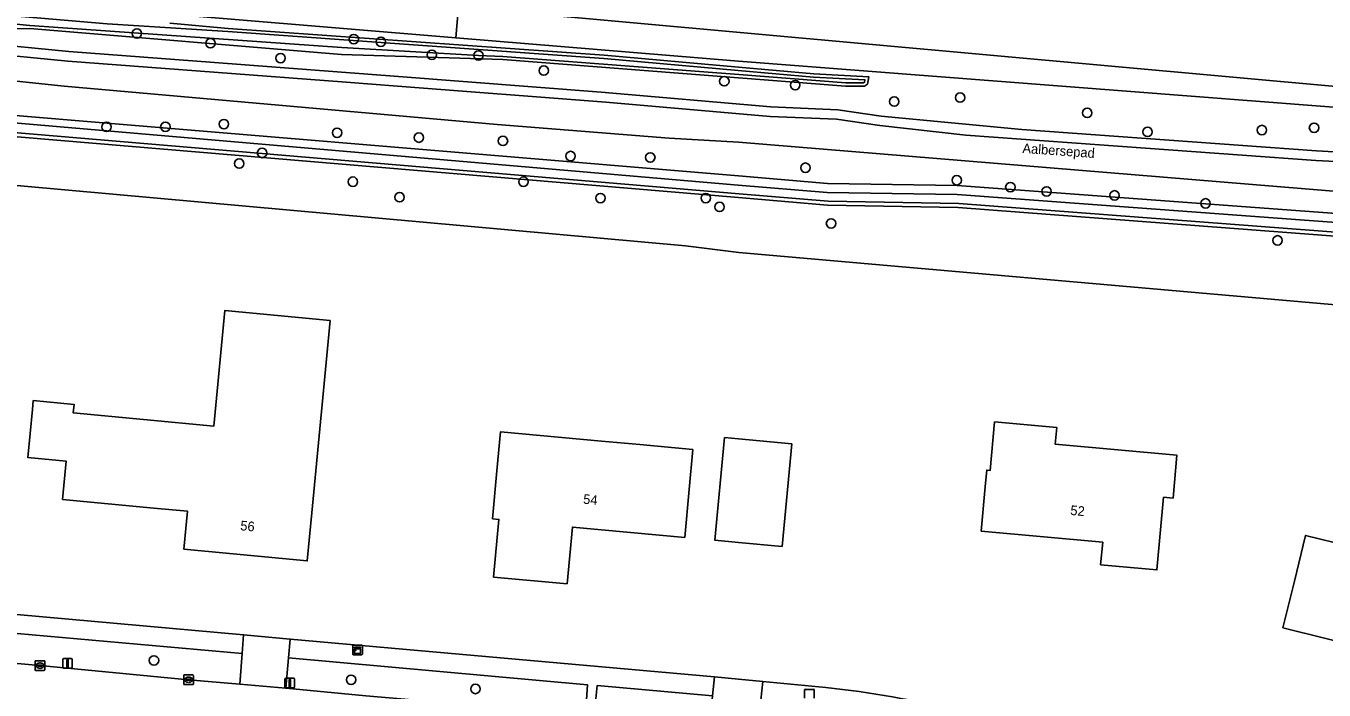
# Model space of a CAD drawing. Extents: x 162722 to 165104, y 384719 to 386284.
# Drawn here: x 163926.1 to 164060.8, y 385187.3 to 385256.2 of the extents above; entities that cross this region are included whole.
import ezdxf

# ---------------------------------------------------------------- set-up
doc = ezdxf.new("R2010")
doc.units = 0
for name, color, linetype in [('IMGEO_Boom', 7, 'Continuous'), ('IMGEO_Brandkraan', 7, 'Continuous'), ('IMGEO_Erf', 7, 'Continuous'), ('IMGEO_Gemengd_bos', 7, 'Continuous'), ('IMGEO_Grasland_agrarisch', 7, 'Continuous'), ('IMGEO_Groenvoorziening', 7, 'Continuous'), ('IMGEO_Kast', 7, 'Continuous'), ('IMGEO_Kolk', 7, 'Continuous'), ('IMGEO_Lichtmast', 7, 'Continuous'), ('IMGEO_Loofbos', 7, 'Continuous'), ('IMGEO_Oever', 7, 'Continuous'), ('IMGEO_Openbare_ruimte_label', 7, 'Continuous'), ('IMGEO_Pand', 7, 'Continuous'), ('IMGEO_Pand_nummerreeks', 7, 'Continuous'), ('IMGEO_Rijbaan_lokaal_gesloten', 7, 'Continuous'), ('IMGEO_Rijbaan_lokaal_halfverhard', 7, 'Continuous'), ('IMGEO_Voetpad_open', 7, 'Continuous'), ('IMGEO_Waterloop', 7, 'Continuous')]:
    doc.layers.add(name, color=color, linetype=linetype)

msp = doc.modelspace()

# ---------------------------------------------------------------- linework, layer by layer
at = {"layer": 'IMGEO_Boom'}
for centre in [(163937.58, 385255.46), (163945.21, 385254.45), (163960.08, 385254.88), (163962.89, 385254.6), (163952.48, 385252.91), (163968.18, 385253.25), (163973.01, 385253.18), (163979.79, 385251.61), (163998.53, 385250.51), (164005.89, 385250.1), (164023, 385248.81), (164016.16, 385248.4), (163946.6, 385246.05), (164036.19, 385247.22), (163934.43, 385245.77), (163940.53, 385245.78), (163958.35, 385245.15), (163966.84, 385244.65), (164042.45, 385245.24), (164054.31, 385245.44), (164059.72, 385245.68), (163975.56, 385244.31), (163948.19, 385241.96), (163950.56, 385243.06), (163982.58, 385242.74), (163990.85, 385242.59), (164006.94, 385241.53), (163959.99, 385240.08), (163977.68, 385240.08), (164022.65, 385240.22), (164028.21, 385239.52), (163964.83, 385238.47), (163985.68, 385238.38), (163996.61, 385238.38), (164031.97, 385239.07), (164039.02, 385238.66), (163998.04, 385237.46), (164048.47, 385237.83), (164009.6, 385235.75), (164055.94, 385233.99), (163939.35, 385190.39), (163959.8, 385188.38), (163972.7, 385187.43)]:
    msp.add_circle(centre, 0.489, dxfattribs=at)
at = {"layer": 'IMGEO_Brandkraan'}
for p, q in [((164006.86, 385186.47), (164006.86, 385187.32)), ((164006.94, 385187.39), (164007.79, 385187.39)), ((164007.86, 385187.32), (164007.86, 385186.47))]:
    msp.add_line(p, q, dxfattribs=at)
for points in [[(164006.86, 385186.47), (164006.86, 385187.32)], [(164006.94, 385187.39), (164007.79, 385187.39)], [(164007.86, 385187.32), (164007.86, 385186.47)]]:
    msp.add_lwpolyline(points, dxfattribs=at)
for centre, start, end in [((164006.94, 385187.32), 91.552, 178.448), ((164006.94, 385187.32), 91.552, 178.448), ((164007.79, 385187.32), 1.552, 88.448), ((164007.79, 385187.32), 1.552, 88.448)]:
    msp.add_arc(centre, 0.0765, start, end, dxfattribs=at)
at = {"layer": 'IMGEO_Erf'}
msp.add_lwpolyline([(164131.6, 385206.91), (164130.71, 385209.11), (164120.89, 385213.87), (164102.71, 385215.68), (164099.68, 385223.88), (164071.61, 385226.26), (164069.06, 385226.66), (164000.03, 385232.74), (163994.49, 385233.42), (163921.24, 385240.04), (163917.36, 385195.85), (163948.65, 385193.05), (163953.49, 385192.61), (163997.5, 385188.68), (164000, 385188.45), (164002.51, 385188.22), (164009.05, 385187.59)], dxfattribs=at)
for points in [[(163955.73, 385205.7), (163955.26, 385200.72), (163942.46, 385201.93), (163942.83, 385205.88), (163939.34, 385206.21), (163929.86, 385207.11), (163930.24, 385211.07), (163926.26, 385211.45), (163926.73, 385216.42), (163926.82, 385217.36), (163931.05, 385216.96), (163930.96, 385216.09), (163945.56, 385214.71), (163946.7, 385226.7), (163957.62, 385225.67)], [(164025.18, 385203.81), (164025.64, 385208.79), (164025.76, 385210.15), (164026.12, 385210.11), (164026.58, 385215.14), (164033.02, 385214.55), (164032.86, 385212.83), (164045.49, 385211.68), (164045.09, 385207.24), (164044.11, 385207.33), (164043.42, 385199.78), (164037.57, 385200.32), (164037.79, 385202.66)], [(163994.88, 385208.13), (163994.42, 385203.15), (163982.76, 385204.23), (163982.21, 385198.35), (163974.59, 385199.05), (163975.14, 385205.02), (163974.48, 385205.09), (163974.94, 385210.06), (163975.32, 385214.13), (163985.78, 385213.16), (163989.76, 385212.79), (163995.26, 385212.28)], [(164004.53, 385202.21), (164000, 385202.64), (163997.56, 385202.86), (163998.55, 385213.52), (164000, 385213.38), (164005.52, 385212.87)], [(164056.48, 385193.77), (164057.68, 385198.62), (164058.84, 385203.37), (164072.42, 385200.03), (164077.49, 385202.76), (164086.52, 385200.54), (164086.3, 385199.67), (164085.11, 385194.81), (164078.55, 385196.42), (164075.39, 385194.51), (164073.01, 385184.84), (164064.14, 385187.01), (164065.27, 385191.61)]]:
    msp.add_lwpolyline(points, close=True, dxfattribs=at)
msp.add_arc((163996.85, 385075.9), 112.35, 69.4969, 83.767, dxfattribs=at)
at = {"layer": 'IMGEO_Gemengd_bos'}
msp.add_lwpolyline([(164100.55, 385231.49), (164022.81, 385237.41), (164009.25, 385237.64), (164000, 385238.42), (163921.82, 385245), (163921.24, 385240.04), (163994.49, 385233.42), (164000.03, 385232.74), (164069.06, 385226.66)], dxfattribs=at)
at = {"layer": 'IMGEO_Grasland_agrarisch'}
for points in [[(164074.75, 385390.56), (164014.8, 385394.87), (164000, 385395.93), (163986.38, 385396.95), (163984.62, 385362.03), (163943.73, 385354), (163942.75, 385342.54), (163942.72, 385342.22), (163934.45, 385258.02), (163970.67, 385255.02), (163970.96, 385258.24), (163974.78, 385302.89), (164000, 385323.52), (164026.82, 385345.17), (164070.61, 385341.89), (164074.39, 385386.44)], [(164066.33, 385295.02), (164004.39, 385300.42), (164000, 385300.8), (163979.59, 385302.53), (163976.14, 385257.74), (164063.13, 385249.85), (164063.14, 385250)]]:
    msp.add_lwpolyline(points, close=True, dxfattribs=at)
at = {"layer": 'IMGEO_Groenvoorziening'}
for points in [[(164073.51, 385238.14), (164000, 385244.17), (163992.8, 385244.6), (163974.96, 385246.02), (163930.03, 385250), (163915.82, 385251.48), (163915.72, 385250.35), (163915.69, 385250.09), (163910.82, 385250.52), (163910.84, 385250.78), (163910.93, 385251.8), (163905.68, 385252.15), (163892.24, 385253.74), (163848.3, 385257.56)], [(163884.6, 385257.26), (163895.05, 385256.23), (163909.94, 385254.43), (163911.16, 385254.33), (163911.2, 385254.75), (163916.07, 385254.41), (163916.03, 385253.92), (163921.2, 385253.48), (163930.41, 385252.6), (163945.57, 385251.44), (163959.29, 385250.4), (163964.63, 385249.99), (163986.23, 385248.34), (164003.27, 385246.86), (164010.18, 385246.55), (164014.67, 385245.9), (164023.58, 385244.91), (164029.32, 385244.49), (164059.9, 385242.29), (164066, 385241.95)], [(164133.98, 385237.82), (164110.27, 385239.27), (164101.43, 385239.79), (164090.14, 385240.67), (164066.08, 385242.94), (164059.97, 385243.29), (164029.39, 385245.49), (164014.82, 385246.89), (164010.32, 385247.54), (164003.34, 385247.86), (163985.76, 385249.38), (163964.71, 385250.98), (163945.64, 385252.44), (163930.5, 385253.6), (163921.3, 385254.48), (163910.06, 385255.42), (163896, 385257.12)], [(163834.56, 385255.03), (163855.76, 385254), (163892.66, 385250), (163911.85, 385247.92), (163911.69, 385246.81), (163911.59, 385246.09), (163912.34, 385245.98), (163914.64, 385245.63), (163915.09, 385245.57), (163915.21, 385246.44), (163915.39, 385247.75), (164000, 385240.67), (164009.22, 385239.9), (164022.69, 385239.69), (164100.92, 385233.9)]]:
    msp.add_lwpolyline(points, dxfattribs=at)
for points in [[(163948.49, 385191.1), (163914.22, 385194.16), (163914.18, 385191.04), (163916.96, 385190.8), (163927.52, 385189.85), (163942.93, 385188.39), (163948.26, 385187.94)], [(163984.32, 385187.87), (163953.32, 385190.65), (163953.03, 385187.5), (163961.33, 385186.71), (163982.73, 385184.89), (163984.11, 385184.77)], [(163997.31, 385186.71), (163985.32, 385187.78), (163985.03, 385184.69), (163997.04, 385183.65)]]:
    msp.add_lwpolyline(points, close=True, dxfattribs=at)
at = {"layer": 'IMGEO_Kast'}
for p, q in [((163959.98, 385191.06), (163959.98, 385191.9)), ((163959.98, 385191.9), (163959.98, 385191.06)), ((163960.05, 385191.98), (163960.89, 385191.98)), ((163960.89, 385191.98), (163960.05, 385191.98)), ((163960.97, 385191.91), (163960.97, 385191.07)), ((163960.97, 385191.07), (163960.97, 385191.91)), ((163960.9, 385190.98), (163960.06, 385190.98)), ((163960.06, 385190.98), (163960.9, 385190.98))]:
    msp.add_line(p, q, dxfattribs=at)
for points in [[(163960.17, 385191.77), (163960.77, 385191.77), (163960.77, 385191.69), (163960.17, 385191.69), (163960.17, 385191.77)], [(163960.17, 385191.6), (163960.77, 385191.6), (163960.77, 385191.11), (163960.17, 385191.11), (163960.17, 385191.6)]]:
    msp.add_lwpolyline(points, dxfattribs=at)
msp.add_circle((163960.25, 385191.44), 0.0377, dxfattribs=at)
for centre, start, end in [((163960.05, 385191.9), 92.4484, 184.2845), ((163960.05, 385191.9), 92.4484, 184.2845), ((163960.9, 385191.9), 2.4484, 94.2845), ((163960.9, 385191.9), 2.4484, 94.2845), ((163960.05, 385191.06), 182.4484, 274.2845), ((163960.05, 385191.06), 182.4484, 274.2845), ((163960.9, 385191.06), 272.4484, 4.2845), ((163960.9, 385191.06), 272.4484, 4.2845)]:
    msp.add_arc(centre, 0.0779, start, end, dxfattribs=at)
at = {"layer": 'IMGEO_Kolk'}
for p, q in [((163927.02, 385189.43), (163927.02, 385190.28)), ((163927.09, 385190.36), (163927.94, 385190.36)), ((163927.51, 385190.13), (163927.53, 385190.13)), ((163928.02, 385190.28), (163928.02, 385189.43)), ((163927.94, 385189.35), (163927.09, 385189.35)), ((163927.28, 385189.85), (163927.28, 385189.86)), ((163927.32, 385189.9), (163927.72, 385189.9)), ((163927.71, 385189.81), (163927.32, 385189.81)), ((163927.53, 385189.58), (163927.5, 385189.58)), ((163927.76, 385189.86), (163927.76, 385189.85)), ((163942.43, 385187.96), (163942.43, 385188.81)), ((163942.51, 385188.89), (163943.36, 385188.89)), ((163942.92, 385188.67), (163942.95, 385188.67)), ((163943.44, 385188.81), (163943.44, 385187.96)), ((163943.36, 385187.89), (163942.51, 385187.89)), ((163942.69, 385188.38), (163942.69, 385188.39)), ((163943.13, 385188.34), (163942.73, 385188.34)), ((163942.74, 385188.43), (163943.13, 385188.43)), ((163942.94, 385188.11), (163942.92, 385188.11)), ((163943.18, 385188.39), (163943.18, 385188.38))]:
    msp.add_line(p, q, dxfattribs=at)
for points in [[(163927.02, 385189.43), (163927.02, 385190.28)], [(163927.09, 385190.36), (163927.94, 385190.36)], [(163928.02, 385190.28), (163928.02, 385189.43)], [(163927.94, 385189.35), (163927.09, 385189.35)], [(163942.43, 385187.96), (163942.43, 385188.81)], [(163942.51, 385188.89), (163943.36, 385188.89)], [(163943.44, 385188.81), (163943.44, 385187.96)], [(163943.36, 385187.89), (163942.51, 385187.89)]]:
    msp.add_lwpolyline(points, dxfattribs=at)
for centre, radius, start, end in [((163927.09, 385190.28), 0.0765, 91.552, 178.448), ((163927.09, 385190.28), 0.0765, 91.552, 178.448), ((163927.94, 385190.28), 0.0765, 1.552, 88.448), ((163927.94, 385190.28), 0.0765, 1.552, 88.448), ((163927.09, 385189.43), 0.0765, 181.552, 268.448), ((163927.09, 385189.43), 0.0765, 181.552, 268.448), ((163927.32, 385189.86), 0.0403, 85.8775, 175.7526), ((163927.31, 385189.85), 0.0366, 178.938, 274.7102), ((163927.72, 385189.85), 0.043, 264.8664, 352.4533), ((163927.72, 385189.86), 0.0386, 1.7309, 96.639), ((163927.94, 385189.43), 0.0765, 271.552, 358.448), ((163927.94, 385189.43), 0.0765, 271.552, 358.448), ((163942.51, 385188.81), 0.0765, 91.552, 178.448), ((163942.51, 385188.81), 0.0765, 91.552, 178.448), ((163943.36, 385188.81), 0.0765, 1.552, 88.448), ((163943.36, 385188.81), 0.0765, 1.552, 88.448), ((163942.51, 385187.96), 0.0765, 181.552, 268.448), ((163942.51, 385187.96), 0.0765, 181.552, 268.448), ((163942.73, 385188.39), 0.0403, 85.8775, 175.7526), ((163942.73, 385188.38), 0.0366, 178.938, 274.7102), ((163943.14, 385188.39), 0.0386, 1.7309, 96.639), ((163943.13, 385188.39), 0.043, 264.8664, 352.4533), ((163943.36, 385187.96), 0.0765, 271.552, 358.448), ((163943.36, 385187.96), 0.0765, 271.552, 358.448)]:
    msp.add_arc(centre, radius, start, end, dxfattribs=at)
for centre, major_axis, ratio, start_param, end_param in [((163927.5, 385189.85), (-0.387, 0.002), 0.722429, 4.712389, 7.853982), ((163927.53, 385189.85), (-0.39, 0.002), 0.717154, 1.570796, 4.712389), ((163942.92, 385188.39), (-0.387, 0.002), 0.722429, 4.712389, 7.853982), ((163942.95, 385188.39), (-0.39, 0.002), 0.717154, 1.570796, 4.712389)]:
    msp.add_ellipse(centre, major_axis=major_axis, ratio=ratio, start_param=start_param, end_param=end_param, dxfattribs=at)
at = {"layer": 'IMGEO_Lichtmast'}
for p, q in [((163929.88, 385189.69), (163929.88, 385190.49)), ((163929.88, 385190.49), (163929.88, 385189.69)), ((163929.98, 385190.59), (163930.77, 385190.59)), ((163930.77, 385190.59), (163929.98, 385190.59)), ((163930.87, 385190.49), (163930.87, 385189.69)), ((163930.87, 385189.69), (163930.87, 385190.49)), ((163930.77, 385189.59), (163929.98, 385189.59)), ((163929.98, 385189.59), (163930.77, 385189.59)), ((163952.94, 385187.64), (163952.94, 385188.44)), ((163952.94, 385188.44), (163952.94, 385187.64)), ((163953.04, 385188.54), (163953.83, 385188.54)), ((163953.83, 385188.54), (163953.04, 385188.54)), ((163953.83, 385187.54), (163953.04, 385187.54)), ((163953.04, 385187.54), (163953.83, 385187.54)), ((163953.93, 385188.44), (163953.93, 385187.64)), ((163953.93, 385187.64), (163953.93, 385188.44))]:
    msp.add_line(p, q, dxfattribs=at)
for points in [[(163930.3, 385190.47), (163930.45, 385190.47), (163930.45, 385189.72), (163930.3, 385189.72), (163930.3, 385190.47)], [(163953.36, 385188.42), (163953.51, 385188.42), (163953.51, 385187.67), (163953.36, 385187.67), (163953.36, 385188.42)]]:
    msp.add_lwpolyline(points, dxfattribs=at)
for centre, start, end in [((163929.98, 385190.49), 90, 180), ((163929.98, 385190.49), 90, 180), ((163930.77, 385190.49), 0, 90), ((163930.77, 385190.49), 360, 90), ((163929.98, 385189.69), 180, 270), ((163929.98, 385189.69), 180, 270), ((163930.77, 385189.69), 270, 0), ((163930.77, 385189.69), 270, 0), ((163953.04, 385188.44), 90, 180), ((163953.04, 385188.44), 90, 180), ((163953.04, 385187.64), 180, 270), ((163953.04, 385187.64), 180, 270), ((163953.83, 385188.44), 0, 90), ((163953.83, 385188.44), 360, 90), ((163953.83, 385187.64), 270, 0), ((163953.83, 385187.64), 270, 0)]:
    msp.add_arc(centre, 0.1, start, end, dxfattribs=at)
at = {"layer": 'IMGEO_Loofbos'}
msp.add_lwpolyline([(164071.39, 385294.52), (164066.33, 385295.02), (164063.14, 385250), (164063.13, 385249.85), (163976.14, 385257.74), (163979.59, 385302.53), (163974.78, 385302.89), (163970.96, 385258.24), (163970.67, 385255.02), (164000, 385252.59), (164033.54, 385250), (164067.56, 385247.38), (164067.7, 385249.46), (164067.74, 385250)], close=True, dxfattribs=at)
for points in [[(163940.99, 385256.54), (163947.03, 385255.98), (163986.06, 385253.21), (164000, 385251.96), (164007.81, 385251.26), (164013.51, 385250.97), (164013.38, 385250.21), (164013.09, 385250), (164011.12, 385250), (164000, 385250.86), (163975.54, 385252.75), (163958.79, 385253.29), (163926.46, 385255.96), (163922.1, 385255.91), (163897.64, 385258.03)], [(164067.56, 385247.38), (164033.54, 385250), (164000, 385252.59), (163970.67, 385255.02), (163934.45, 385258.02)], [(163896, 385257.12), (163910.06, 385255.42), (163921.3, 385254.48), (163930.5, 385253.6), (163945.64, 385252.44), (163964.71, 385250.98), (163985.76, 385249.38), (164003.34, 385247.86), (164010.32, 385247.54), (164014.82, 385246.89), (164029.39, 385245.49), (164059.97, 385243.29), (164066.08, 385242.94), (164090.14, 385240.67), (164101.43, 385239.79), (164110.27, 385239.27), (164133.98, 385237.82)]]:
    msp.add_lwpolyline(points, dxfattribs=at)
at = {"layer": 'IMGEO_Oever'}
for points in [[(163878.73, 385260.86), (163878.79, 385261.28), (163881.82, 385261.12), (163897, 385259.62), (163899.03, 385259.42), (163925.99, 385257.2), (163934.49, 385256.47), (163941.07, 385256.03), (163947.01, 385255.65), (163986.03, 385252.88), (163999.97, 385251.63), (164007.79, 385250.93), (164013.12, 385250.66), (164013.08, 385250.4), (164012.98, 385250.33), (164011.13, 385250.33), (164000.02, 385251.19), (163975.56, 385253.08), (163973.01, 385253.18), (163958.83, 385254.02), (163926.47, 385256.29), (163922.25, 385256.71), (163897.77, 385258.55), (163879.26, 385260.32)], [(163897.64, 385258.03), (163922.1, 385255.91), (163926.46, 385255.96), (163958.79, 385253.29), (163975.54, 385252.75), (164000, 385250.86), (164011.12, 385250), (164013.09, 385250), (164013.38, 385250.21), (164013.51, 385250.97), (164007.81, 385251.26), (164000, 385251.96), (163986.06, 385253.21), (163947.03, 385255.98), (163940.99, 385256.54)], [(164100.92, 385233.9), (164022.69, 385239.69), (164009.22, 385239.9), (164000, 385240.67), (163915.39, 385247.75), (163915.21, 385246.44), (163915.09, 385245.57), (163921.82, 385245), (164000, 385238.42), (164009.25, 385237.64), (164022.81, 385237.41), (164100.55, 385231.49)], [(163916.32, 385246.93), (163999.97, 385239.73), (164009.21, 385238.96), (164022.68, 385238.75), (164100.9, 385232.96), (164130.94, 385231.14)], [(164130.8, 385230.39), (164100.62, 385231.9), (164022.87, 385237.82), (164009.31, 385238.05), (164000.08, 385238.83), (163921.9, 385245.41), (163916.39, 385245.87)]]:
    msp.add_lwpolyline(points, dxfattribs=at)
at = {"layer": 'IMGEO_Pand'}
for points in [[(163930.24, 385211.07), (163929.86, 385207.11), (163939.34, 385206.21), (163942.83, 385205.88), (163942.46, 385201.93), (163955.26, 385200.72), (163955.73, 385205.7), (163957.62, 385225.67), (163946.7, 385226.7), (163945.56, 385214.71), (163930.96, 385216.09), (163931.05, 385216.96), (163926.82, 385217.36), (163926.73, 385216.42), (163926.26, 385211.45)], [(164025.18, 385203.81), (164037.79, 385202.66), (164037.57, 385200.32), (164043.42, 385199.78), (164044.11, 385207.33), (164045.09, 385207.24), (164045.49, 385211.68), (164032.86, 385212.83), (164033.02, 385214.55), (164026.58, 385215.14), (164026.12, 385210.11), (164025.76, 385210.15), (164025.64, 385208.79)], [(163974.48, 385205.09), (163975.14, 385205.02), (163974.59, 385199.05), (163982.21, 385198.35), (163982.76, 385204.23), (163994.42, 385203.15), (163994.88, 385208.13), (163995.26, 385212.28), (163989.76, 385212.79), (163985.78, 385213.16), (163975.32, 385214.13), (163974.94, 385210.06)], [(164004.53, 385202.21), (164005.52, 385212.87), (164000, 385213.38), (163998.55, 385213.52), (163997.56, 385202.86), (164000, 385202.64)], [(164056.48, 385193.77), (164065.27, 385191.61), (164064.14, 385187.01), (164073.01, 385184.84), (164075.39, 385194.51), (164078.55, 385196.42), (164085.11, 385194.81), (164086.3, 385199.67), (164086.52, 385200.54), (164077.49, 385202.76), (164072.42, 385200.03), (164058.84, 385203.37), (164057.68, 385198.62)]]:
    msp.add_lwpolyline(points, close=True, dxfattribs=at)
at = {"layer": 'IMGEO_Rijbaan_lokaal_gesloten'}
msp.add_lwpolyline([(164069.54, 385160.27), (164053.65, 385167.55), (164050.88, 385168.81), (164049.03, 385169.66), (164038.92, 385174.28), (164037.91, 385174.76), (164034.06, 385176.36), (164024.33, 385179.48), (164014.36, 385181.72), (164009.37, 385182.49), (164006.36, 385182.82), (164004.16, 385183.01), (164002.02, 385183.19), (164000, 385183.38), (163997.04, 385183.65), (163985.03, 385184.69), (163984.11, 385184.77), (163982.73, 385184.89), (163961.33, 385186.71), (163953.03, 385187.5), (163948.26, 385187.94), (163942.93, 385188.39), (163927.52, 385189.85), (163916.96, 385190.8)], dxfattribs=at)
at = {"layer": 'IMGEO_Rijbaan_lokaal_halfverhard'}
for points in [[(164029.32, 385244.49), (164023.58, 385244.91), (164014.67, 385245.9), (164010.18, 385246.55), (164003.27, 385246.86), (163986.23, 385248.34), (163964.63, 385249.99), (163959.29, 385250.4), (163945.57, 385251.44), (163930.41, 385252.6), (163921.2, 385253.48), (163916.03, 385253.92), (163915.82, 385251.48), (163930.03, 385250), (163974.96, 385246.02), (163992.8, 385244.6), (164000, 385244.17), (164073.51, 385238.14), (164078.34, 385237.74), (164127.03, 385233.75), (164131.8, 385233.18), (164134.24, 385238.01)], [(164130.93, 385236.98), (164130.03, 385237.06), (164124.61, 385237.33), (164106.9, 385238.49), (164101.38, 385238.79), (164090.05, 385239.68), (164073.14, 385241.32), (164066, 385241.95), (164059.9, 385242.29), (164029.32, 385244.49)]]:
    msp.add_lwpolyline(points, dxfattribs=at)
at = {"layer": 'IMGEO_Voetpad_open'}
for points in [[(163917.36, 385195.85), (163914.81, 385196.08), (163912.45, 385196.29), (163906.37, 385196.83), (163904.79, 385196.97), (163904.61, 385195.02), (163914.22, 385194.16), (163948.49, 385191.1), (163948.65, 385193.05)], [(163953.03, 385187.5), (163953.32, 385190.65), (163953.49, 385192.61), (163948.65, 385193.05), (163948.49, 385191.1), (163948.26, 385187.94)], [(163997.31, 385186.71), (163997.5, 385188.68), (163953.49, 385192.61), (163953.32, 385190.65), (163984.32, 385187.87), (163984.11, 385184.77), (163985.03, 385184.69), (163985.32, 385187.78)], [(164000, 385183.38), (164002.02, 385183.19), (164002.32, 385186.26), (164002.51, 385188.22), (164000, 385188.45), (163997.5, 385188.68), (163997.31, 385186.71), (163997.04, 385183.65)]]:
    msp.add_lwpolyline(points, close=True, dxfattribs=at)
msp.add_lwpolyline([(164009.05, 385187.59), (164002.51, 385188.22), (164002.32, 385186.26), (164009.8, 385185.51)], dxfattribs=at)
msp.add_arc((163996.85, 385075.9), 112.35, 69.4969, 83.767, dxfattribs=at)
at = {"layer": 'IMGEO_Waterloop'}
for points in [[(163879.26, 385260.32), (163897.77, 385258.55), (163922.25, 385256.71), (163926.47, 385256.29), (163958.83, 385254.02), (163973.01, 385253.18), (163975.56, 385253.08), (164000.02, 385251.19), (164011.13, 385250.33), (164012.98, 385250.33), (164013.08, 385250.4), (164013.12, 385250.66), (164007.79, 385250.93), (163999.97, 385251.63), (163986.03, 385252.88), (163947.01, 385255.65), (163941.07, 385256.03), (163934.49, 385256.47), (163925.99, 385257.2), (163899.03, 385259.42), (163897, 385259.62), (163881.82, 385261.12), (163878.79, 385261.28), (163878.73, 385260.86)], [(164130.94, 385231.14), (164100.9, 385232.96), (164022.68, 385238.75), (164009.21, 385238.96), (163999.97, 385239.73), (163916.32, 385246.93)], [(163916.39, 385245.87), (163921.9, 385245.41), (164000.08, 385238.83), (164009.31, 385238.05), (164022.87, 385237.82), (164100.62, 385231.9), (164130.8, 385230.39)]]:
    msp.add_lwpolyline(points, dxfattribs=at)

# ---------------------------------------------------------------- texts
at = {"layer": 'IMGEO_Openbare_ruimte_label'}
msp.add_text('Aalbersepad', height=1, rotation=355.9266, dxfattribs=at).set_placement((164029.44, 385243.07))
at = {"layer": 'IMGEO_Pand_nummerreeks'}
for s, rotation, p in [('54', 354.701, (163983.85, 385206.66)), ('52', 354.7859, (164034.4, 385205.5)), ('56', 354.6019, (163948.27, 385203.91))]:
    msp.add_text(s, height=1, rotation=rotation, dxfattribs=at).set_placement(p)

doc.saveas('drawing.dxf')
